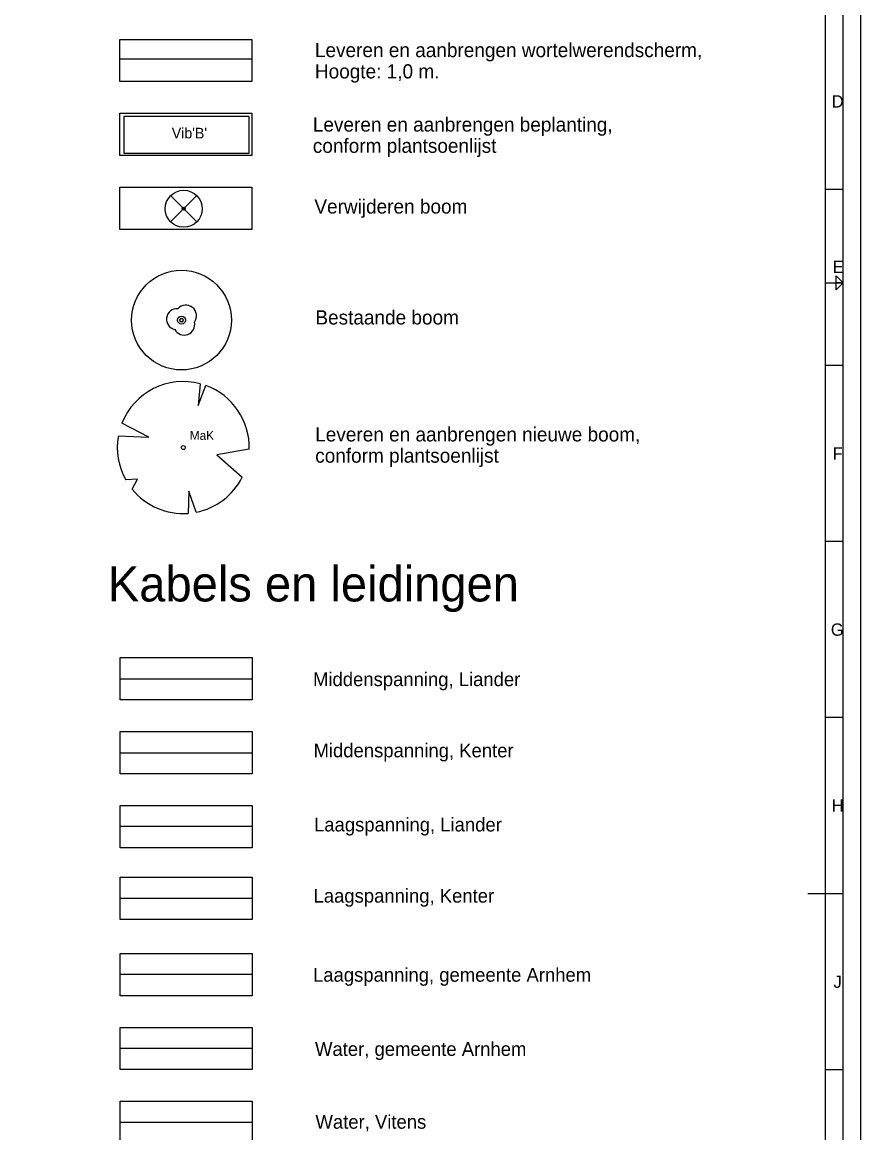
# Model space of a CAD drawing. Extents: x 192672 to 192910, y 446344 to 446512.
# Drawn here: x 192861.9 to 192909.5, y 446414.1 to 446477.2 of the extents above; entities that cross this region are included whole.
import ezdxf

# ---------------------------------------------------------------- set-up
doc = ezdxf.new("R2010")
doc.units = 0
for name, color, linetype in [('201011 legenda', 7, 'Continuous'), ('205134 wortelgeleidingsscherm', 7, 'Continuous'), ('B-GV-GR-BOOM-S', 7, 'Continuous'), ('B-OI-KL-ET_LS-G', 7, 'Continuous'), ('B-OI-KL-ET_MS-G', 7, 'Continuous'), ('B-OI-KL-WATER-G', 7, 'Continuous'), ('boom', 7, 'Continuous'), ('N-GV-GR-BEPLANTING-G', 7, 'Continuous'), ('N-GV-GR-BOOM-S', 7, 'Continuous'), ('TEKST', 7, 'Continuous'), ('X-XX-AL-TEKENBLAD-S', 7, 'Continuous')]:
    doc.layers.add(name, color=color, linetype=linetype)

msp = doc.modelspace()

# ---------------------------------------------------------------- linework, layer by layer
at = {"layer": '201011 legenda'}
for points in [[(192867.462, 446476.179), (192874.962, 446476.179), (192874.962, 446473.779), (192867.462, 446473.779)], [(192867.462, 446471.979), (192874.962, 446471.979), (192874.962, 446469.579), (192867.462, 446469.579)], [(192867.462, 446467.779), (192874.962, 446467.779), (192874.962, 446465.379), (192867.462, 446465.379)], [(192867.469, 446441.064), (192874.969, 446441.064), (192874.969, 446438.664), (192867.469, 446438.664)], [(192867.469, 446436.864), (192874.969, 446436.864), (192874.969, 446434.464), (192867.469, 446434.464)], [(192867.469, 446432.664), (192874.969, 446432.664), (192874.969, 446430.264), (192867.469, 446430.264)], [(192867.469, 446428.587), (192874.969, 446428.587), (192874.969, 446426.187), (192867.469, 446426.187)], [(192867.469, 446424.264), (192874.969, 446424.264), (192874.969, 446421.864), (192867.469, 446421.864)], [(192867.469, 446420.064), (192874.969, 446420.064), (192874.969, 446417.664), (192867.469, 446417.664)], [(192867.469, 446415.864), (192874.969, 446415.864), (192874.969, 446413.464), (192867.469, 446413.464)]]:
    msp.add_lwpolyline(points, close=True, dxfattribs=at)
at = {"layer": '205134 wortelgeleidingsscherm'}
msp.add_line((192867.462, 446475.064), (192874.962, 446475.064), dxfattribs=at)
at = {"layer": 'B-GV-GR-BOOM-S'}
for p, q in [((192871.852, 446467.325), (192870.317, 446465.79)), ((192871.852, 446465.79), (192870.317, 446467.325))]:
    msp.add_line(p, q, dxfattribs=at)
for centre, radius in [((192871.085, 446466.557), 1.05), ((192871.085, 446466.557), 0.084), ((192870.961, 446460.232), 2.832), ((192870.961, 446460.232), 0.227)]:
    msp.add_circle(centre, radius, dxfattribs=at)
at = {"layer": 'B-OI-KL-ET_LS-G'}
for p, q in [((192874.969, 446431.464), (192867.469, 446431.464)), ((192874.969, 446427.387), (192867.469, 446427.387)), ((192874.969, 446423.064), (192867.469, 446423.064))]:
    msp.add_line(p, q, dxfattribs=at)
at = {"layer": 'B-OI-KL-ET_MS-G'}
for p, q in [((192867.469, 446439.864), (192874.969, 446439.864)), ((192867.469, 446435.664), (192874.969, 446435.664))]:
    msp.add_line(p, q, dxfattribs=at)
at = {"layer": 'B-OI-KL-WATER-G'}
for points in [[(192874.969, 446418.864), (192867.469, 446418.864)], [(192874.969, 446414.664), (192867.469, 446414.664)]]:
    msp.add_lwpolyline(points, dxfattribs=at)
at = {"layer": 'boom'}
msp.add_circle((192870.961, 446460.232), 0.1, dxfattribs=at)
for centre, radius, start, end in [((192871.211, 446460.482), 0.6, 323.54458, 138.4658), ((192870.711, 446460.282), 0.6, 85.13702, 257.75442), ((192871.111, 446459.982), 0.6, 208.50578, 13.83556), ((192870.961, 446460.232), 0.1, 0, 180), ((192870.961, 446460.232), 0.1, 180, 0)]:
    msp.add_arc(centre, radius, start, end, dxfattribs=at)
at = {"layer": 'N-GV-GR-BEPLANTING-G'}
msp.add_lwpolyline([(192867.689, 446469.713), (192874.799, 446469.713), (192874.799, 446471.791), (192867.689, 446471.791)], close=True, dxfattribs=at)
at = {"layer": 'N-GV-GR-BOOM-S'}
for points in [[(192872.021, 446456.62), (192871.91, 446455.384), (192872.35, 446456.517)], [(192867.374, 446453.663), (192869.104, 446453.581), (192867.579, 446454.382)], [(192874.809, 446452.9), (192872.97, 446452.587), (192874.408, 446451.306)], [(192868.16, 446450.624), (192868.455, 446451.196), (192867.798, 446451.154)], [(192871.801, 446449.321), (192871.374, 446450.517), (192871.331, 446449.257)]]:
    msp.add_lwpolyline(points, dxfattribs=at)
msp.add_circle((192871.062, 446452.996), 0.112, dxfattribs=at)
for start, end in [(75.18441, 158.29895), (358.52408, 69.90661), (169.74905, 209.43023), (281.36007, 333.20465), (219.26669, 274.10684)]:
    msp.add_arc((192871.062, 446452.996), 3.748, start, end, dxfattribs=at)
at = {"layer": 'X-XX-AL-TEKENBLAD-S'}
for p, q in [((192909.543, 446343.556), (192909.543, 446511.756)), ((192908.543, 446344.556), (192908.543, 446510.756)), ((192908.543, 446467.656), (192907.543, 446467.656)), ((192907.543, 446462.356), (192908.543, 446462.356)), ((192908.143, 446462.356), (192908.543, 446462.356)), ((192908.543, 446462.356), (192908.143, 446462.356)), ((192908.543, 446457.656), (192907.543, 446457.656)), ((192908.543, 446447.656), (192907.543, 446447.656)), ((192908.543, 446437.656), (192907.543, 446437.656)), ((192908.543, 446417.656), (192907.543, 446417.656))]:
    msp.add_line(p, q, dxfattribs=at)
msp.add_lwpolyline([(192675.743, 446345.556), (192907.543, 446345.556), (192907.543, 446509.756), (192675.743, 446509.756)], close=True, dxfattribs=at)
for points in [[(192908.143, 446462.356), (192908.143, 446462.756), (192908.543, 446462.356)], [(192908.543, 446462.356), (192908.143, 446461.956), (192908.143, 446462.356)], [(192908.543, 446427.656), (192906.543, 446427.656)]]:
    msp.add_lwpolyline(points, dxfattribs=at)

# ---------------------------------------------------------------- texts
at = {"layer": '201011 legenda'}
for s, height, p in [('Leveren en aanbrengen wortelwerendscherm, ', 0.8064, (192878.54, 446475.168)), ('Hoogte: 1,0 m. ', 0.8064, (192878.54, 446473.961)), ('Leveren en aanbrengen beplanting, ', 0.8064, (192878.421, 446470.941)), ('conform plantsoenlijst', 0.8064, (192878.421, 446469.734)), ('Verwijderen boom', 0.8064, (192878.508, 446466.285)), ('Bestaande boom', 0.8064, (192878.565, 446459.984)), ('Leveren en aanbrengen nieuwe boom, ', 0.8064, (192878.556, 446453.342)), ('conform plantsoenlijst', 0.8064, (192878.556, 446452.135)), ('Kabels en leidingen', 2, (192866.78, 446444.254)), ('Middenspanning, Liander', 0.784, (192878.432, 446439.443)), ('Middenspanning, Kenter', 0.784, (192878.46, 446435.4)), ('Laagspanning, Liander', 0.784, (192878.488, 446431.19)), ('Laagspanning, Kenter', 0.784, (192878.46, 446427.147)), ('Laagspanning, gemeente Arnhem', 0.784, (192878.432, 446422.656)), ('Water, gemeente Arnhem', 0.784, (192878.545, 446418.443)), ('Water, Vitens', 0.784, (192878.572, 446414.307))]:
    msp.add_text(s, height=height, dxfattribs=at).set_placement(p)
at = {"layer": 'TEKST'}
for s, height, p in [("Vib'B'", 0.6, (192870.41, 446470.555)), ('MaK', 0.5, (192871.433, 446453.434))]:
    msp.add_text(s, height=height, dxfattribs=at).set_placement(p)
at = {"layer": 'X-XX-AL-TEKENBLAD-S'}
for s, p in [('D', (192907.893, 446472.306)), ('E', (192907.943, 446462.906)), ('F', (192907.943, 446452.306)), ('G', (192907.843, 446442.306)), ('H', (192907.893, 446432.306)), ('J', (192907.993, 446422.306))]:
    msp.add_text(s, height=0.7, dxfattribs=at).set_placement(p)

doc.saveas('drawing.dxf')
